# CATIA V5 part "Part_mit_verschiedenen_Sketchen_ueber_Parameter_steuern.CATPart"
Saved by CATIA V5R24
Part number: Part_mit verschiedenen_Sketchen_über Parameter_gesteuern
Publications: "Sketch_Var"
Bounding box of the stored display mesh (mm): x -29.282 to 29.282, y -29.28 to 29.28, z -34.414 to 0
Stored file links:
  D:\V5_Sort_von sams133\CATIA_V5_erledigtd Fragstellungen\Catpart_mit_Parametersketch\Part_mit_verschiedenen_Sketchen_ueber_Parameter_steuern.CATPart
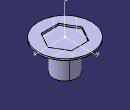
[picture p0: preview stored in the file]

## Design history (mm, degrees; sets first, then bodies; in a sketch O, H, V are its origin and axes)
Parameters
  PROFILE = "Hex"
AxisSystem1: origin (0, 0, 0), X (1, 0, 0), Y (0, 1, 0), Z (0, 0, 1)
Set1 "ProfilesShape"
  DatumCurve1 "Shape"
  Sketch1 "Torx" on XY plane of AxisSystem1, origin (0, 0, 0), H (1, 0, 0), V (0, 1, 0)
    circle A1 centre (0, 0) radius 12.5
    radius A1 = 12.5
  Sketch2 "Phillips" on XY plane of AxisSystem1, origin (0, 0, 0), H (1, 0, 0), V (0, 1, 0)
    line L1 (15, 15) -> (15, -15)
    line L2 (15, -15) -> (-15, -15)
    line L3 (-15, -15) -> (-15, 15)
    line L4 (-15, 15) -> (15, 15)
    distance L4 L2 = 30
    distance L3 L1 = 30
    vertical: L1 V, L3 V
    horizontal: L2 H, L4 H
    equidistance: L1 L3 O, L2 L4 O
  Sketch3 "Hex" on XY plane of AxisSystem1, origin (0, 0, 0), H (1, 0, 0), V (0, 1, 0)
    point P1 (19.2548, 0)
    point P2 (9.6274, 16.6752)
    point P3 (-9.6274, 16.6752)
    point P4 (-19.2548, 0)
    point P5 (-9.6274, -16.6752)
    point P6 (9.6274, -16.6752)
    point P7 (14.4411, 8.3376)
    line L1 (19.2548, 0) -> (9.6274, 16.6752)
    line L2 (9.6274, 16.6752) -> (-9.6274, 16.6752)
    line L3 (-9.6274, 16.6752) -> (-19.2548, 0)
    line L4 (-19.2548, 0) -> (-9.6274, -16.6752)
    line L5 (-9.6274, -16.6752) -> (9.6274, -16.6752)
    line L6 (9.6274, -16.6752) -> (19.2548, 0)
    construction line L7 (0, 0) -> (14.4411, 8.3376)
    construction circle A1 centre (0, 0) radius 19.2548
    construction arc A2 centre (-9.6274, -16.6752) radius 19.2548 from (-19.2548, 0) to (9.6274, -16.6752) cw
    construction arc A3 centre (9.6274, 16.6752) radius 19.2548 from (-9.6274, 16.6752) to (19.2548, 0) ccw
    distance L2 L5 = 33.3504
    coincidence: A1 P1, A1 P2, A1 P3, A1 P4, A1 P5, A1 P6, A2 O, A3 O, P1 H
    midpoint: P7 L1
    parallelism: L1 L4
Body1 (main body)
  Sketch4 on YZ plane of AxisSystem1, origin (0, 0, 0), H (0, 1, 0), V (0, 0, 1)
    line L1 (0, 0) -> (29.2837, 0)
    line L2 (29.2837, 0) -> (29.2837, -1.7109)
    line L3 (29.2837, -1.7109) -> (12.9032, -11.1028)
    point P3 (12.9032, -11.1028)
    line L4 (12.9032, -11.1028) -> (12.9032, -33.0172)
    line L5 (12.9032, -33.0172) -> (10.4668, -34.4142)
    line L6 (10.4668, -34.4142) -> (0, -34.4142)
    point P6 (0, -34.4142)
    axis line L7 (0, 40.1914) -> (0, -86.238)
    point P7 (0, 40.1914)
    distance L1 L6 = 34.4142
    radius about axis L4 L7 = 12.9032
    angle L4 L3 = 119.8283
    radius about axis L2 L7 = 29.2837
    distance P3 L1 = 11.1028
    horizontal: L1 H, L6 H
    vertical: L2 V, L4 V, L7 V
    parallelism: L5 L3
    coincidence: P6 V, P7 V
  Shaft1: profile Sketch4, axis Sketch4.L7, angle 360
  Pocket1: profile DatumCurve1, length 2
Relations
  rule "verschiedene Sketche waehlen":
    /*Regel erzeugt von: mbe 30.09.2014*/
    if PROFILE == "Phillips"
    	DatumCurve1  = Sketch2
    if PROFILE == "Torx"
    	DatumCurve1 = Sketch1
    if PROFILE == "Hex"
    	DatumCurve1 = Sketch3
